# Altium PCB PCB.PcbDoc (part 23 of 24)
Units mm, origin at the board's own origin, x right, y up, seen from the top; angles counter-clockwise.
Board outline 100 x 160 mm, 10 copper layers (TOP_L1, L2, L3, L4, L5, L6, L7, L8, L9, BOTTOM_L10), stack 1.946 mm thick; 1358 components, 1149 nets, 6777 pads, 10914 vias.
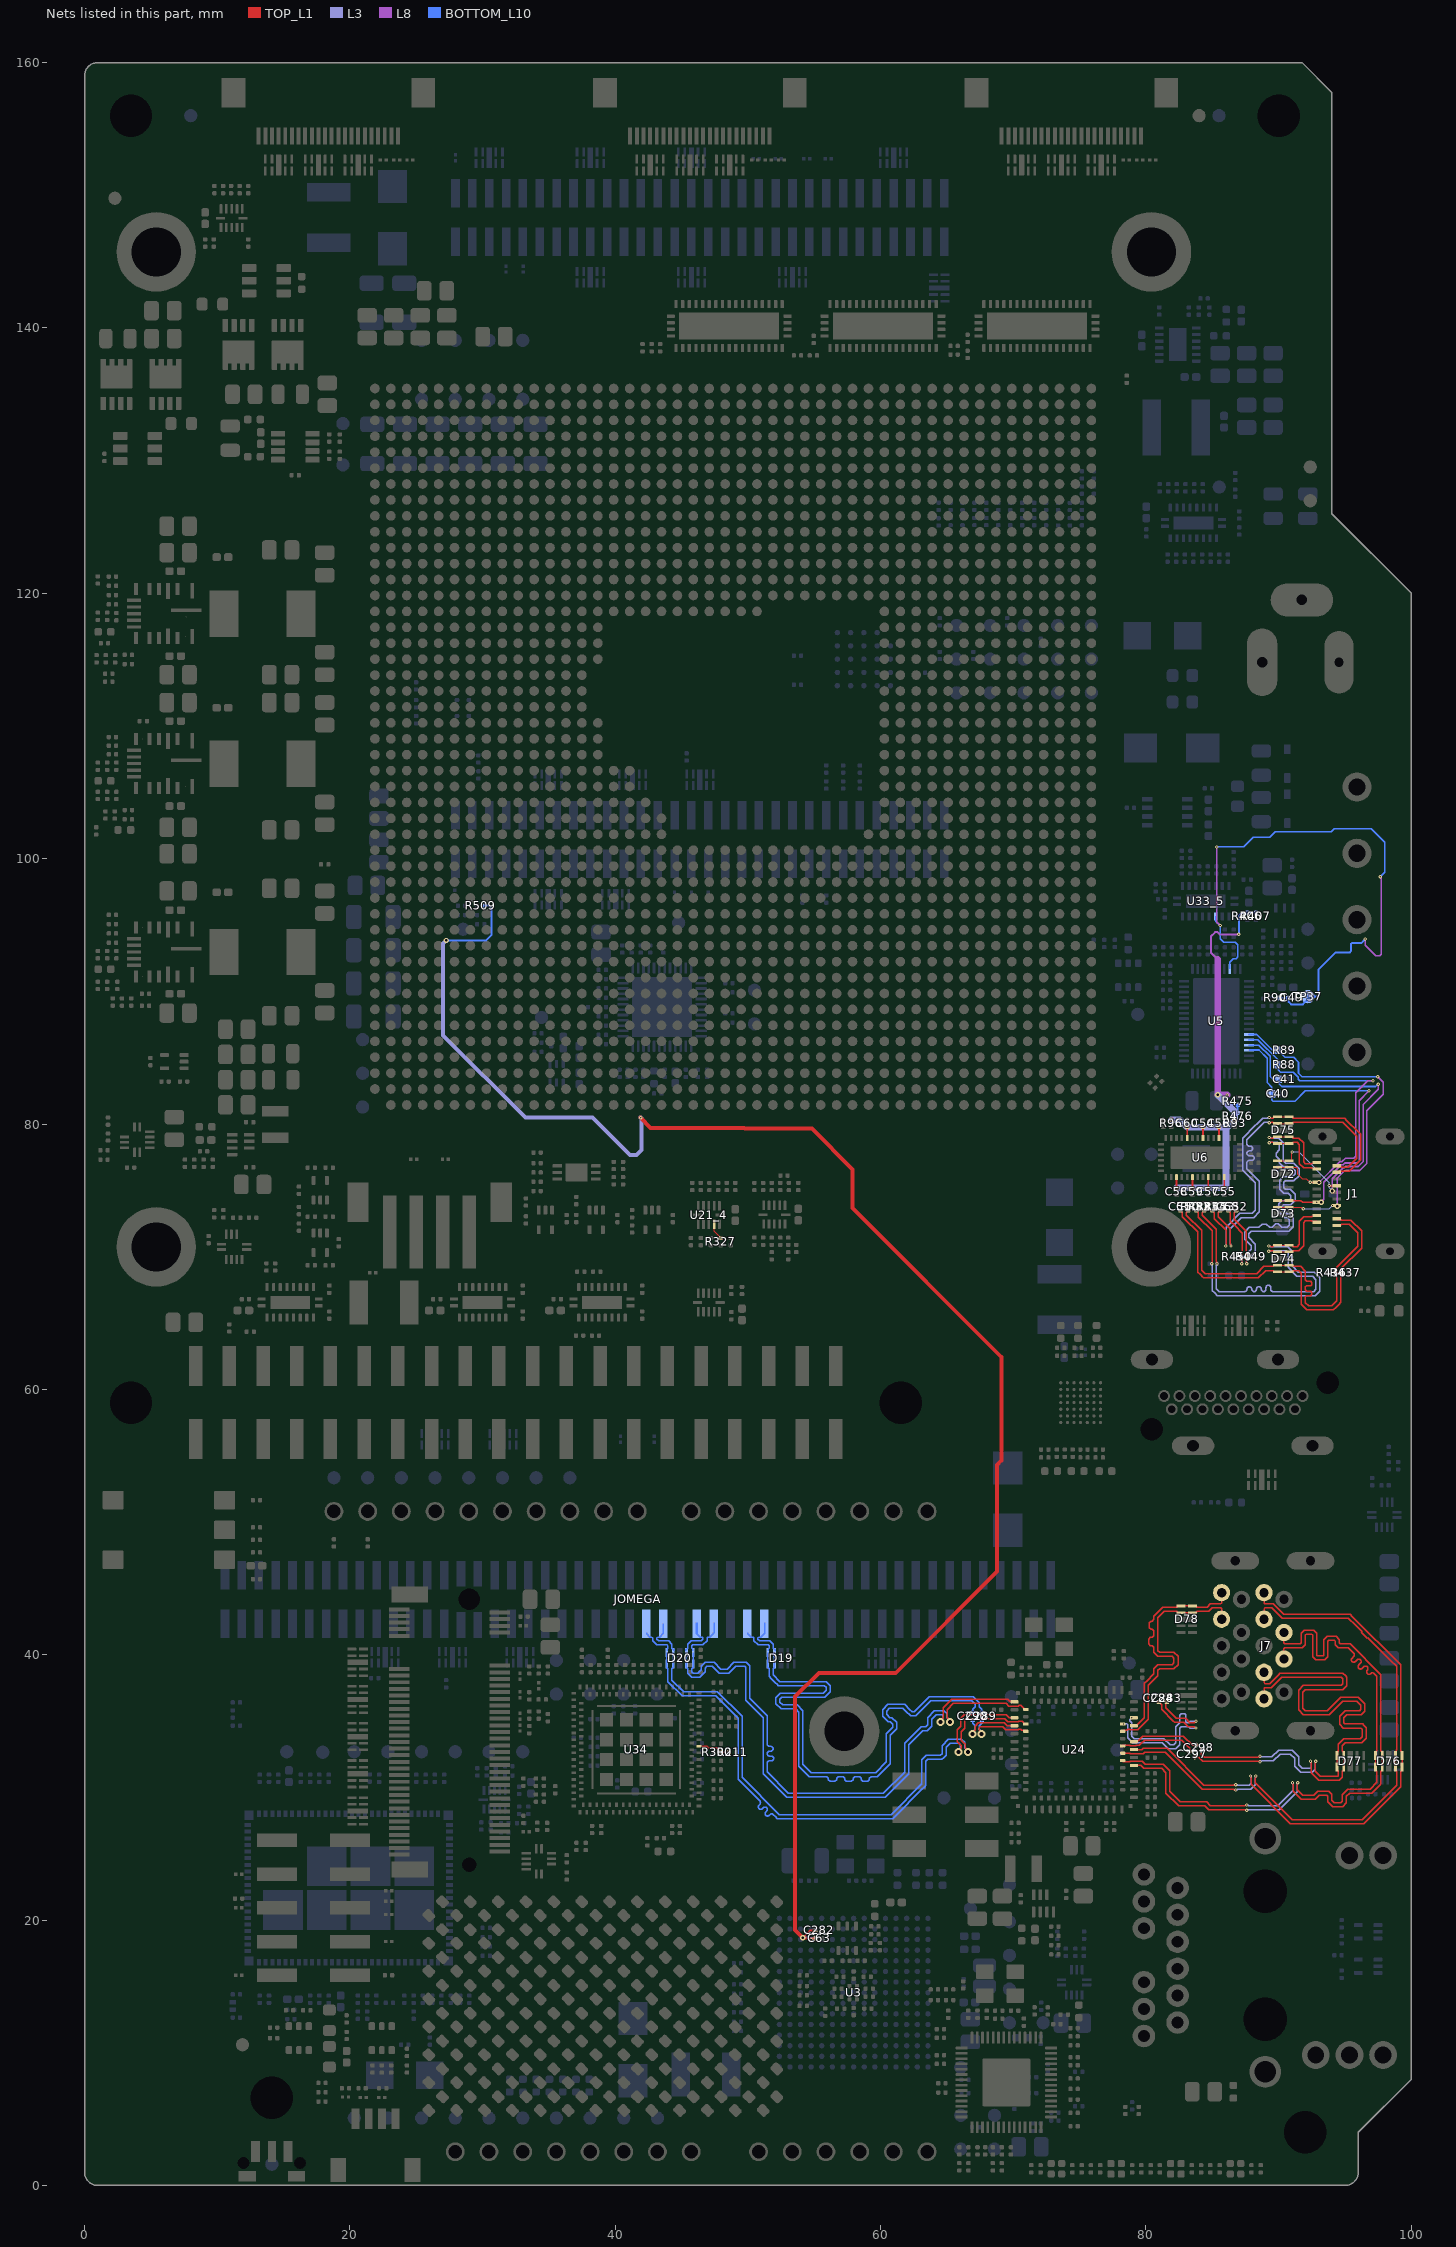
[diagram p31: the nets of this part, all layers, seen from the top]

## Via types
v1: diameter 0.25, hole 0.1, TOP_L1 to L2, tented both sides, 3439 vias
v2: diameter 0.25, hole 0.1, L2 to L3, tented both sides, 2256 vias
v3: diameter 0.25, hole 0.1, L9 to BOTTOM_L10, tented both sides, 1685 vias
v4: diameter 0.25, hole 0.1, L8 to L9, tented both sides, 1675 vias
v5: diameter 0.4, hole 0.2, L3 to L8, tented both sides, 1251 vias
v6: diameter 0.6, hole 0.3, TOP_L1 to BOTTOM_L10, tented both sides, 600 vias
v7: diameter 0.24, hole 0.1, TOP_L1 to L2, tented both sides, 8 vias

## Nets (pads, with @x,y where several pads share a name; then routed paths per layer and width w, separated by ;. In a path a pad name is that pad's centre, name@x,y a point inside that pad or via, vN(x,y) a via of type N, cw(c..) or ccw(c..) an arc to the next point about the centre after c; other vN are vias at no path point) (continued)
USB2_SSRX_N: D78.5 D78.6 J7.14 U24.A10 | length 18.6
  TOP_L1 w0.109: U24.A10@79.091,34.649 79.267,34.649 79.873,35.255 79.873,37.832 80.052,38.011 80.595,38.554 80.595,38.651 80.595,38.952 80.897,39.254 81.984,39.254 82.107,39.377 82.107,39.748 81.984,39.871 80.897,39.871 80.595,40.173 80.595,40.443 80.595,40.509 80.595,40.563 80.472,40.687 80.332,40.687 80.208,40.81 80.208,41.18 80.332,41.304 80.472,41.304 80.595,41.427 80.595,41.798 80.472,41.921 80.38,41.921 80.256,42.045 80.256,42.415 80.38,42.538 80.472,42.538 80.595,42.662 80.595,42.915 80.774,43.094 80.779,43.099 81.079,43.399 81.257,43.577 82.303,43.577 82.401,43.675 D78.6@82.638,43.675 D78.5@83.392,43.675 ; D78.5@83.513,43.675 83.751,43.675 83.849,43.577 84.602,43.577 84.852,43.827 85.636,43.827 85.7,43.891 J7.14@85.7,44.675
USB2_SSRX_P: D78.4 D78.7 J7.15 U24.B9 | length 18.7
  TOP_L1 w0.109: U24.B9@78.241,34.224 78.307,34.29 78.538,34.29 78.621,34.373 78.761,34.373 78.797,34.336 78.874,34.336 78.882,34.344 79.394,34.344 80.178,35.129 80.178,37.706 80.9,38.428 80.9,38.651 80.9,38.826 81.023,38.949 82.11,38.949 82.412,39.251 82.412,39.874 82.11,40.176 81.023,40.176 80.9,40.299 80.9,40.443 80.9,42.789 81.384,43.273 82.303,43.273 82.401,43.175 D78.7@82.638,43.175 D78.4@83.392,43.175 ; D78.4@83.513,43.175 83.751,43.175 83.849,43.273 84.729,43.273 84.979,43.523 85.636,43.523 85.7,43.459 J7.15@85.7,42.675
USB2_SSTX_26_N: C284.1 U24.B10 | length 12.1
  TOP_L1 w0.109: C284.1@80.975,36.425 81.172,36.229 81.172,35.889 82.072,34.99 82.161,34.9 82.862,34.9 83.188,34.575 83.637,34.575 83.737,34.475 v1(83.775,34.475)
  L3 w0.104: v2(78.301,34.774) 78.329,34.802 78.473,34.802 78.478,34.807 78.565,34.807 78.626,34.746 78.626,33.743 79.005,33.364 81.228,33.364 81.688,32.904 82.225,32.904 82.548,33.227 82.548,34.448 82.675,34.575 83.233,34.575 83.333,34.475 v1(83.775,34.475)
  other v1: 78.301,34.774
  other v2: 83.775,34.475
USB2_SSTX_26_P: C283.1 U24.A11 | length 12.5
  TOP_L1 w0.109: C283.1@81.575,36.425 81.477,36.327 81.477,36.016 82.034,35.459 82.288,35.205 82.988,35.205 83.314,34.88 83.642,34.88 83.737,34.975 v1(83.775,34.975)
  L3 w0.104: v2(78.921,35.249) 78.784,35.111 78.784,35.02 78.931,34.872 78.931,33.869 79.131,33.669 81.354,33.669 81.814,33.209 82.099,33.209 82.243,33.353 82.243,34.574 82.549,34.88 82.549,35.444 82.662,35.557 82.902,35.557 83,35.459 83,34.941 83.061,34.88 83.233,34.88 83.329,34.975 v1(83.775,34.975)
  other v1: 78.921,35.249
  other v2: 83.775,34.975
USB3_CAP_SSTX_N: C290.2 D19.5 D19.6 JOMEGA.38 | length 41.5
  BOTTOM_L10 w0.109: JOMEGA.38@49.998,41.643 49.998,41.569 50.237,41.33 50.385,41.33 50.449,41.266 50.449,41.049 50.76,40.738 51.53,40.738 51.594,40.674 51.594,40.498 51.538,40.442 D19.6@51.538,40.307 ; D19.6@51.496,40.137 D19.5@51.496,39.288 51.496,39.05 51.594,38.953 51.594,38.361 51.773,38.182 52.052,37.903 52.197,37.758 52.286,37.669 55.766,37.669 55.904,37.531 55.904,37.328 55.662,37.086 52.435,37.086 52.1,36.751 52.1,36.305 52.495,35.91 53.588,35.91 53.83,35.668 53.83,35.346 53.83,31.604 54.631,30.803 55.098,30.803 55.942,30.803 56.065,30.68 56.065,30.587 56.188,30.463 56.559,30.463 56.682,30.587 56.682,30.68 56.806,30.803 57.176,30.803 57.299,30.68 57.299,30.587 57.423,30.463 57.793,30.463 57.917,30.587 57.917,30.68 58.04,30.803 58.41,30.803 58.534,30.68 58.534,30.587 58.657,30.463 59.028,30.463 59.151,30.587 59.151,30.68 59.275,30.803 59.329,30.803 59.74,30.803 60.735,31.798 60.735,33.933 61.032,34.23 61.211,34.409 61.211,34.898 60.85,35.259 60.688,35.259 60.45,35.498 60.45,35.743 60.666,35.959 61.675,35.959 61.883,35.751 62.252,35.382 62.649,35.382 63.791,36.524 66.855,36.524 67.123,36.256 67.123,36.075 66.925,35.877 C290.2@66.925,35.622
USB3_CAP_SSTX_P: C289.2 D19.4 D19.7 JOMEGA.36 | length 41.1
  BOTTOM_L10 w0.109: JOMEGA.36@51.268,42.393 51.268,41.632 50.966,41.33 50.818,41.33 50.754,41.266 50.754,41.176 50.887,41.043 51.656,41.043 51.899,40.8 51.899,40.498 52.038,40.359 D19.7@52.038,40.307 ; D19.4@51.996,39.288 51.996,39.05 51.899,38.953 51.899,38.487 52.413,37.974 55.892,37.974 56.209,37.657 56.209,37.202 55.788,36.781 52.561,36.781 52.405,36.625 52.405,36.431 52.621,36.215 53.714,36.215 54.135,35.794 54.135,35.22 54.135,31.73 54.757,31.108 59.614,31.108 60.43,31.924 60.43,34.059 60.906,34.535 60.906,34.772 60.723,34.954 60.562,34.954 60.145,35.371 60.145,35.869 60.539,36.264 61.801,36.264 62.206,35.859 62.378,35.687 62.523,35.687 63.665,36.829 65.866,36.829 66.981,36.829 67.427,36.382 67.427,36.075 67.625,35.877 C289.2@67.625,35.622 ; D19.4@51.996,39.314 D19.7@51.996,40.163
USB3_D_N: D20.2 D20.9 JOMEGA.44 U24.A27 | length 46.5
  TOP_L1 w0.109: v6(64.514,34.929) 64.514,35.041 64.711,35.239 64.711,35.995 65.345,36.629 69.589,36.629 69.729,36.488 70.052,36.488 U24.A27@70.091,36.449
  BOTTOM_L10 w0.109: D20.9@45.325,40.306 45.325,40.358 45.464,40.498 45.464,40.8 45.707,41.043 46.476,41.043 46.609,41.175 46.609,41.266 46.545,41.33 46.397,41.33 46.168,41.559 46.095,41.632 JOMEGA.44@46.095,42.393 ; D20.2@45.366,39.313 D20.9@45.366,40.163 ; D20.9@45.366,40.137 D20.2@45.366,39.288 45.366,39.05 45.464,38.952 45.464,38.598 45.765,38.297 46.352,38.297 46.786,38.731 46.786,38.995 46.906,39.115 47.319,39.115 47.838,38.597 48.548,38.597 49.072,39.121 49.762,39.121 49.826,39.057 49.826,36.574 50.7,35.7 51.145,35.255 51.145,31.035 51.234,30.946 52.435,29.745 52.748,29.433 52.926,29.254 60.338,29.254 62.111,31.026 62.111,33.202 63.19,34.281 63.523,34.281 63.847,34.604 63.847,35.136 64.18,35.469 64.638,35.469 64.702,35.405 64.702,35.239 64.514,35.051 v6(64.514,34.929) ; JOMEGA.44@46.178,41.569 JOMEGA.44@46.178,42.393
USB3_D_P: D20.1 D20.10 JOMEGA.42 U24.B25 | length 46.5
  TOP_L1 w0.109: v6(65.214,34.929) 65.214,35.041 65.016,35.239 65.016,35.869 65.471,36.324 69.463,36.324 69.658,36.129 70.378,36.129 70.433,36.183 70.557,36.183 70.866,35.874 U24.B25@70.941,35.874
  BOTTOM_L10 w0.109: D20.10@45.825,40.307 45.825,40.442 45.769,40.498 45.769,40.674 45.833,40.738 46.602,40.738 46.914,41.049 46.914,41.266 46.978,41.33 47.126,41.33 47.365,41.569 JOMEGA.42@47.365,41.643 ; D20.10@45.866,40.137 D20.1@45.866,39.288 45.866,39.05 45.769,38.952 45.769,38.724 45.891,38.602 46.226,38.602 46.481,38.857 46.481,39.121 46.78,39.42 47.445,39.42 47.964,38.902 48.422,38.902 48.946,39.426 49.889,39.426 50.131,39.183 50.131,36.7 51.36,35.471 51.45,35.381 51.45,34.447 51.45,33.271 ccw(c51.631,33.271) 51.631,33.089 51.711,33.089 cw(c51.711,32.908) 51.711,32.726 51.631,32.726 ccw(c51.631,32.544) 51.631,32.363 51.751,32.363 cw(c51.751,32.181) 51.751,31.999 51.631,31.999 ccw(c51.631,31.818) 51.45,31.818 51.45,31.4 51.45,31.162 53.052,29.559 60.212,29.559 61.806,31.153 61.806,33.328 63.063,34.585 63.397,34.585 63.542,34.73 63.542,35.262 64.054,35.774 64.764,35.774 65.007,35.531 65.007,35.239 65.214,35.032 v6(65.214,34.929) ; JOMEGA.42@47.448,41.632 JOMEGA.42@47.448,42.393
USB3_SSRX_N: D20.5 D20.6 JOMEGA.50 U24.A29 | length 46.5
  TOP_L1 w0.109: v6(65.871,32.674) 65.871,32.786 66.069,32.983 66.069,33.143 65.957,33.256 65.778,33.434 65.778,34.328 65.785,34.334 66.048,34.598 66.048,35.228 66.291,35.47 69.485,35.47 69.698,35.257 70.083,35.257 U24.A29@70.091,35.249
  BOTTOM_L10 w0.109: JOMEGA.50@42.368,41.643 42.368,41.569 42.607,41.33 42.755,41.33 42.819,41.266 42.819,41.049 43.13,40.738 43.9,40.738 43.964,40.674 43.964,40.498 43.908,40.442 D20.6@43.908,40.307 ; D20.6@43.866,40.137 D20.5@43.866,39.288 43.866,39.05 43.964,38.952 43.964,37.965 45.03,36.898 47.574,36.898 49.255,35.218 49.255,30.619 49.277,30.597 49.316,30.558 50.893,28.981 cw(c50.765,28.852) 50.893,28.724 50.832,28.663 ccw(c50.961,28.534) 50.832,28.406 ccw(c50.961,28.534) 51.089,28.406 51.15,28.467 cw(c51.279,28.339) 51.407,28.467 cw(c51.279,28.339) 51.407,28.21 51.346,28.149 ccw(c51.475,28.021) 51.346,27.892 ccw(c51.475,28.021) 51.603,27.892 51.664,27.953 cw(c51.792,27.825) 51.921,27.953 51.959,27.915 52.046,27.828 52.225,27.649 60.911,27.649 61.089,27.828 63.077,29.815 63.327,30.065 63.416,30.154 63.416,31.953 63.569,32.106 64.617,32.106 64.756,32.245 64.935,32.423 64.935,33.029 65.23,33.324 65.954,33.324 66.018,33.26 66.018,32.954 65.871,32.807 v6(65.871,32.674)
USB3_SSRX_P: D20.4 D20.7 JOMEGA.48 U24.B27 | length 46.6
  TOP_L1 w0.109: v6(66.571,32.674) 66.571,32.786 66.374,32.983 66.374,33.27 66.083,33.56 66.083,34.202 66.09,34.208 66.353,34.471 66.353,35.102 66.417,35.166 69.358,35.166 69.595,34.929 70.378,34.929 70.422,34.973 70.668,34.973 70.866,34.774 U24.B27@70.941,34.774
  BOTTOM_L10 w0.109: JOMEGA.48@43.606,42.35 43.606,41.6 43.336,41.33 43.188,41.33 43.124,41.266 43.124,41.175 43.257,41.043 44.026,41.043 44.269,40.8 44.269,40.498 44.408,40.358 D20.7@44.408,40.306 ; D20.4@44.366,39.288 44.366,39.05 44.269,38.952 44.269,38.091 45.157,37.203 47.7,37.203 49.56,35.344 49.56,30.746 52.351,27.954 60.785,27.954 63.111,30.281 63.111,32.079 63.443,32.411 64.491,32.411 64.63,32.55 64.63,33.155 65.103,33.629 66.081,33.629 66.323,33.386 66.323,32.991 66.571,32.743 v6(66.571,32.674) ; D20.4@44.366,39.313 D20.7@44.366,40.163
USB3_SSTX_26_N: C290.1 U24.A30 | length 5
  TOP_L1 w0.109: v6(66.919,34.034) 66.919,34.146 67.116,34.344 67.116,34.617 67.359,34.86 69.316,34.86 69.542,34.633 70.076,34.633 U24.A30@70.091,34.649
  BOTTOM_L10 w0.109: v6(66.919,34.034) 66.919,34.167 67.116,34.365 67.116,34.645 66.925,34.836 C290.1@66.925,35.072
USB3_SSTX_26_P: C289.1 U24.B28 | length 5.5
  TOP_L1 w0.109: v6(67.619,34.034) 67.619,34.146 67.421,34.344 67.421,34.491 67.485,34.555 69.19,34.555 69.416,34.329 70.378,34.329 70.422,34.373 70.562,34.373 70.645,34.29 70.876,34.29 U24.B28@70.941,34.224
  BOTTOM_L10 w0.109: v6(67.619,34.034) 67.619,34.167 67.421,34.365 67.421,34.645 67.625,34.849 C289.1@67.625,35.072
USB4_CAP_SSTX_N: C298.2 D77.2 D77.9 J7.8 | length 42.1
  TOP_L1 w0.109: C298.2@84.18,32.784 84.179,32.505 84.395,32.29 88.445,32.29 88.471,32.315 88.57,32.315 v1(88.597,32.342) ; J7.8@88.9,38.675 88.9,37.891 88.964,37.827 89.33,37.827 89.921,38.418 90.01,38.507 90.099,38.597 94.847,38.597 95.043,38.4 95.134,38.31 95.134,37.667 95.02,37.554 94.842,37.375 91.99,37.375 91.8,37.185 91.8,35.959 91.984,35.775 93.669,35.775 94.684,36.791 96.016,36.791 96.505,36.301 96.505,35.749 96.231,35.475 95.126,35.475 94.9,35.249 94.9,34.875 94.995,34.78 96.326,34.78 96.416,34.691 96.605,34.501 96.605,33.707 96.426,33.529 96.261,33.364 95.03,33.364 94.802,33.136 94.802,32.748 94.9,32.65 D77.9@94.9,32.412 D77.2@94.9,31.537 94.9,31.3 94.802,31.202 94.802,30.765 94.56,30.523 93.021,30.523 92.448,31.096 92.448,31.841 92.427,31.861 92.427,31.948 v2(92.4,31.975)
  L3 w0.104: v1(88.597,32.342) 88.645,32.295 89.477,32.295 90,32.818 91.011,32.818 91.516,32.313 91.516,31.706 91.785,31.437 92.387,31.437 92.448,31.498 92.448,31.841 92.428,31.861 92.428,31.947 v2(92.4,31.975)
  other v1: 92.4,31.975
  other v2: 88.597,32.342
USB4_CAP_SSTX_P: C297.2 D77.1 D77.10 J7.9 | length 41.3
  TOP_L1 w0.109: C297.2@83.686,32.29 83.964,32.29 84.268,31.985 88.455,31.985 88.471,31.969 88.57,31.969 v1(88.597,31.942) ; J7.9@88.9,36.675 88.9,37.459 88.964,37.523 89.456,37.523 90.226,38.292 94.721,38.292 94.739,38.274 94.829,38.184 94.829,37.793 94.716,37.68 91.864,37.68 91.495,37.311 91.495,35.833 91.858,35.47 93.795,35.47 94.811,36.486 95.889,36.486 95.9,36.475 96.2,36.175 96.2,35.875 96.105,35.78 95,35.78 94.595,35.375 94.595,34.749 94.869,34.475 96.2,34.475 96.3,34.375 96.3,33.833 96.135,33.669 94.904,33.669 94.498,33.262 94.498,32.748 94.4,32.65 D77.10@94.4,32.412 D77.1@94.4,31.537 94.4,31.3 94.498,31.202 94.498,30.891 94.434,30.827 93.148,30.827 92.752,31.223 92.752,31.841 92.773,31.861 92.773,31.948 v2(92.8,31.975)
  L3 w0.104: v1(88.597,31.942) 88.625,31.97 88.711,31.97 88.731,31.99 89.603,31.99 90.126,32.513 90.884,32.513 91.211,32.187 91.211,31.58 91.659,31.132 92.513,31.132 92.752,31.371 92.752,31.841 92.772,31.861 92.772,31.947 v2(92.8,31.975)
  other v1: 92.8,31.975
  other v2: 88.597,31.942
USB4_D_N: D76.1 D76.10 J7.2 U24.A5 | length 47.3
  TOP_L1 w0.109: U24.A5@79.091,31.649 79.107,31.665 79.599,31.665 79.725,31.539 79.814,31.449 81.17,31.449 81.499,31.12 81.499,29.57 82.469,28.6 84.447,28.6 84.724,28.323 87.466,28.323 87.486,28.302 87.573,28.302 v1(87.6,28.275) ; J7.2@90.4,39.675 90.4,40.459 90.464,40.523 91.5,40.523 91.77,40.523 92.013,40.765 92.013,41.494 92.067,41.549 92.505,41.549 92.56,41.494 92.56,39.85 92.793,39.617 93.483,39.617 93.717,39.85 93.717,41.017 93.771,41.072 94.209,41.072 94.264,41.017 94.264,40.765 94.506,40.523 95.252,40.523 95.276,40.499 95.356,40.419 95.395,40.38 95.652,40.123 cw(c95.523,39.995) 95.652,39.866 95.53,39.744 ccw(c95.658,39.616) 95.53,39.487 ccw(c95.658,39.616) 95.787,39.487 95.909,39.609 cw(c96.037,39.481) 96.166,39.609 cw(c96.037,39.481) 96.166,39.353 96.045,39.232 ccw(c96.173,39.103) 96.045,38.975 ccw(c96.173,39.103) 96.302,38.975 96.422,39.096 cw(c96.551,38.967) 96.679,39.096 cw(c96.551,38.967) 96.679,38.839 ccw(c96.808,38.71) 96.679,38.582 ccw(c96.808,38.71) 96.936,38.582 cw(c97.064,38.454) 97.193,38.582 97.398,38.377 97.398,38.263 97.398,32.748 97.3,32.65 D76.10@97.3,32.412 D76.1@97.3,31.537 97.3,31.3 97.398,31.202 97.398,30.369 96.903,29.874 95.212,29.874 94.979,29.641 94.8,29.462 94.8,28.952 94.691,28.843 94.191,28.843 94.005,29.029 94.005,29.477 93.762,29.72 92.945,29.72 92.8,29.575 92.711,29.486 92.625,29.4 91.83,29.4 91.393,29.837 91.393,30.214 91.413,30.235 91.413,30.322 v2(91.44,30.349)
  L3 w0.104: v1(87.6,28.275) 87.628,28.303 87.714,28.303 87.734,28.323 90.045,28.323 91.393,29.67 91.393,30.215 91.412,30.235 91.412,30.321 v2(91.44,30.349)
  other v1: 91.44,30.349
  other v2: 87.6,28.275
USB4_D_P: D76.2 D76.9 J7.3 U24.B5 | length 47.3
  TOP_L1 w0.109: U24.B5@78.241,31.974 78.29,31.925 78.761,31.925 78.805,31.969 79.725,31.969 79.941,31.754 81.296,31.754 81.804,31.246 81.804,29.696 82.192,29.308 82.3,29.2 82.595,28.905 84.573,28.905 84.85,28.627 87.466,28.627 87.486,28.648 87.573,28.648 v1(87.6,28.675) ; J7.3@90.4,41.675 90.4,40.891 90.464,40.827 91.5,40.827 91.644,40.827 91.708,40.891 91.708,41.62 91.941,41.853 92.631,41.853 92.865,41.62 92.865,39.977 92.919,39.922 93.357,39.922 93.412,39.977 93.412,41.144 93.645,41.377 94.335,41.377 94.569,41.144 94.569,40.891 94.633,40.827 95.276,40.827 95.379,40.827 97.702,38.504 97.702,32.748 97.8,32.65 D76.9@97.8,32.412 D76.2@97.8,31.537 97.8,31.3 97.702,31.202 97.702,30.546 97.702,30.243 97.029,29.57 95.338,29.57 95.105,29.336 95.105,28.826 94.817,28.538 94.064,28.538 93.7,28.902 93.7,29.351 93.636,29.415 93.071,29.415 92.751,29.095 91.703,29.095 91.088,29.71 91.088,30.214 91.067,30.235 91.067,30.322 v1(91.04,30.349)
  L3 w0.104: v1(87.6,28.675) 87.628,28.647 87.714,28.647 87.734,28.627 89.919,28.627 91.088,29.796 91.088,30.215 91.068,30.235 91.068,30.321 v1(91.04,30.349)
  other v2: 87.6,28.675 91.04,30.349
USB4_SSRX_N: D76.5 D76.6 J7.5 U24.A7 | length 47.3
  TOP_L1 w0.109: U24.A7@79.091,32.849 79.107,32.833 79.672,32.833 79.786,32.947 81.584,32.947 84.371,30.16 86.631,30.16 86.652,30.181 86.739,30.181 v2(86.766,30.208) ; v1(87.882,30.86) 87.909,30.834 87.909,30.734 87.93,30.713 87.93,30.228 90.89,27.268 96.424,27.268 99.202,30.046 99.202,31.202 99.3,31.3 D76.5@99.3,31.537 99.3,32.65 99.186,32.764 99.186,39.255 95.562,42.88 95.383,43.058 91.848,43.058 90.379,43.058 89.61,43.827 88.964,43.827 88.9,43.891 J7.5@88.9,44.675
  L3 w0.104: v2(86.766,30.208) 86.794,30.18 86.88,30.18 86.9,30.16 87.782,30.16 87.93,30.308 87.93,30.727 87.91,30.746 87.91,30.833 v1(87.882,30.86)
  other v1: 86.766,30.208
  other v2: 87.882,30.86
USB4_SSRX_P: D76.4 D76.7 J7.6 U24.B6 | length 47.3
  TOP_L1 w0.109: U24.B6@78.241,32.574 78.759,32.574 78.805,32.529 79.798,32.529 79.912,32.642 81.458,32.642 84.245,29.856 86.631,29.856 86.652,29.835 86.739,29.835 v2(86.766,29.808) ; v1(88.282,30.86) 88.255,30.834 88.255,30.734 88.234,30.713 88.234,30.354 91.016,27.573 96.298,27.573 98.898,30.173 98.898,31.202 98.8,31.3 D76.4@98.8,31.537 D76.7@98.8,32.412 98.845,32.458 98.845,32.786 98.881,32.822 98.881,39.129 98.413,39.598 98.374,39.636 96.717,41.294 96.664,41.241 96.227,41.677 96.28,41.73 95.844,42.167 95.805,42.205 95.257,42.753 90.253,42.753 89.483,43.523 88.964,43.523 88.9,43.459 J7.6@88.9,42.675
  L3 w0.104: v2(86.766,29.808) 86.794,29.836 86.88,29.836 86.9,29.856 87.908,29.856 88.234,30.182 88.234,30.727 88.254,30.746 88.254,30.833 v1(88.282,30.86)
  other v1: 86.766,29.808
  other v2: 88.282,30.86
USB4_SSTX_26_N: C298.1 U24.A8 | length 5.2
  TOP_L1 w0.109: U24.A8@79.091,33.449 79.157,33.515 79.414,33.515 79.478,33.579 79.592,33.693 79.771,33.872 82.813,33.872 83.512,33.172 C298.1@83.791,33.172
USB4_SSTX_26_P: C297.1 U24.B7 | length 5.8
  TOP_L1 w0.109: U24.B7@78.241,33.124 78.29,33.173 78.761,33.173 78.805,33.129 79.221,33.129 79.25,33.158 79.489,33.158 79.604,33.274 79.897,33.567 82.687,33.567 83.297,32.957 C297.1@83.297,32.679
USBC_CC1: C40.2 D73.5 D73.6 J1.A5 U5.40 | length 26.4
  TOP_L1 w0.086: D73.6@89.907,74.229 D73.5@90.782,74.229
  TOP_L1 w0.109: D73.5@90.782,74.229 91.676,74.229 91.801,74.104 J1.A5@92.863,74.104
  L3 w0.109: v1(92.864,74.103) 92.866,74.102 93.21,74.102 v5(93.211,74.1)
  L8 w0.127: v5(93.211,74.1) 93.211,74.147 93.4,74.336 93.4,75.608 94.725,76.933 94.857,76.933 94.986,77.062 95.922,77.062 96.071,77.21 96.071,81.759 v4(96.811,82.5)
  BOTTOM_L10 w0.127: U5.40@87.791,85.577 88.516,85.577 89.132,84.962 89.132,83.132 89.483,82.78 C40.2@89.483,82.267 89.483,81.817 89.578,81.723 91.229,81.723 92.006,82.5 v4(96.811,82.5)
  other v2: 92.864,74.103
  other v3: 96.811,82.5
USBC_CC2: C41.2 D72.5 D72.6 J1.B5 U5.39 | length 28.7
  TOP_L1 w0.086: D72.6@89.907,77.229 D72.5@90.782,77.229 ; D72.5@90.982,77.229 90.979,77.232 90.979,77.838 v2(91.032,77.891) ; v1(93.819,75.359) 94.371,75.359 J1.B5@94.376,75.354
  L3 w0.086: v2(91.032,77.891) 91.514,77.891 93.819,75.586 v1(93.819,75.359) 93.819,75.185 94.041,74.963 v5(94.031,74.953)
  L8 w0.127: v5(94.031,74.953) 94.031,75.872 94.865,76.706 94.951,76.706 95.038,76.793 95.991,76.793 96.367,77.169 96.367,81.467 97.511,82.611 v4(97.511,83)
  BOTTOM_L10 w0.127: U5.39@87.753,85.947 88.509,85.947 89.359,85.097 89.359,83.576 89.568,83.367 C41.2@89.803,83.367 ; C41.2@90.029,83.341 90.029,83.024 90.231,82.822 97.3,82.822 97.478,83 v4(97.511,83)
  other v1: 91.032,77.891
  other v2: 93.819,75.359
  other v3: 97.511,83
USBC_SBU1: D72.4 D72.7 J1.A8 R88.2 U5.38 | length 25.6
  TOP_L1 w0.086: D72.7@89.907,76.729 D72.4@90.782,76.729 91.326,76.729 91.451,76.604 91.451,76.204 91.775,75.881 92.097,75.881 v2(92.373,75.604) J1.A8@92.876,75.604
  L3 w0.086: v2(92.373,75.604) 93.026,75.604 v5(93.036,75.594)
  L8 w0.127: v5(93.036,75.594) 94.602,77.16 94.763,77.16 95.031,77.428 95.652,77.428 95.801,77.576 95.801,82.351 96.705,83.256 v4(97.112,83.256)
  BOTTOM_L10 w0.127: U5.38@87.753,86.347 87.756,86.344 88.432,86.344 89.92,84.857 89.92,84.688 89.779,84.547 R88.2@89.779,84.483 ; R88.2@89.963,84.467 89.963,84.077 90.14,83.9 91.097,83.9 91.48,83.517 91.48,83.368 91.591,83.256 v4(97.112,83.256)
  other v1: 92.373,75.604
  other v3: 97.112,83.256
USBC_SBU2: D73.4 D73.7 J1.B8 R89.2 U5.37 | length 28.2
  TOP_L1 w0.086: D73.7@89.907,73.729 D73.4@90.782,73.729 91.718,73.729 91.836,73.611 v2(91.847,73.611)
  L3 w0.086: v2(91.847,73.611) 91.848,73.61 93.807,73.61 v1(94.051,73.854) 94.078,73.827 94.384,73.827 v5(94.411,73.8)
  L8 w0.127: v5(94.411,73.8) 94.411,75.927 94.963,76.479 95.045,76.479 95.065,76.498 96.11,76.498 96.629,77.018 96.629,80.999 97.871,82.241 97.871,83.154 v4(97.468,83.556)
  BOTTOM_L10 w0.127: U5.37@87.753,86.747 88.355,86.747 89.535,85.567 89.928,85.567 90.472,85.023 91.13,85.023 91.5,84.653 91.5,83.817 91.761,83.556 v4(97.468,83.556)
  other v1: 91.847,73.611
  other v2: 94.051,73.854
  other v3: 97.468,83.556
USBC_SSRX1_N: C51.2 D74.1 D74.10 J1.B10 R437.1 | length 27.6
  TOP_L1 w0.086: D74.10@89.907,68.859 D74.1@90.782,68.859
  TOP_L1 w0.109: C51.2@82.6,73.492 82.748,73.345 82.748,73.012 82.926,72.833 83.895,71.864 83.895,68.84 84.074,68.661 84.148,68.587 84.246,68.489 84.335,68.4 88.459,68.4 88.473,68.414 89.016,68.957 89.572,68.957 89.67,68.859 D74.10@89.907,68.859 ; D74.1@90.782,68.859 91.02,68.859 91.117,68.957 91.52,68.957 91.712,68.764 91.712,66.41 92.134,65.988 94.123,65.988 94.302,66.167 94.511,66.376 94.689,66.554 94.689,69.086 96.251,70.647 96.251,71.648 96.251,71.944 95.438,72.756 94.878,72.756 94.742,72.756 94.715,72.784 94.446,72.784 J1.B10@94.376,72.854
USBC_SSRX1_P: C50.2 D74.2 D74.9 J1.B11 R436.1 | length 27.6
  TOP_L1 w0.086: D74.9@89.907,69.359 D74.2@90.782,69.359
  TOP_L1 w0.109: C50.2@83.2,73.492 83.052,73.345 83.052,73.138 84.2,71.991 84.2,68.966 84.461,68.705 88.333,68.705 88.346,68.719 88.889,69.261 89.572,69.261 89.67,69.359 D74.9@89.907,69.359 ; D74.2@90.782,69.359 91.02,69.359 91.117,69.261 91.646,69.261 92.017,68.891 92.017,68.246 92.113,68.15 92.401,68.15 92.505,68.046 92.505,67.896 92.409,67.8 92.1,67.8 92.017,67.717 92.017,67.5 92.113,67.404 92.401,67.404 92.505,67.3 92.505,67.15 92.409,67.054 92.1,67.054 92.017,66.971 92.017,66.536 92.26,66.293 93.997,66.293 94.385,66.68 94.385,69.212 95.946,70.773 95.946,71.818 95.312,72.452 95.004,72.452 94.742,72.452 94.715,72.424 94.446,72.424 J1.B11@94.376,72.354
USBC_SSRX2_N: C53.2 D75.1 D75.10 J1.A10 R450.1 | length 27.2
  TOP_L1 w0.086: D75.10@89.907,78.536 D75.1@90.782,78.536
  TOP_L1 w0.109: C53.2@86.2,73.492 86.348,73.345 86.348,72.687 86.684,72.35 87.252,71.783 87.252,69.583 v1@87.232,69.564 ; v2(89.283,78.586) 89.31,78.613 89.397,78.613 89.418,78.634 ; 89.435,78.634 89.572,78.634 89.67,78.536 D75.10@89.907,78.536 ; D75.1@90.782,78.536 91.02,78.536 91.117,78.634 91.382,78.634 91.567,78.449 91.567,77.021 91.885,76.702 92.51,76.702 92.537,76.674 92.806,76.674 J1.A10@92.876,76.604
  L3 w0.104: v2(87.205,69.463) 87.233,69.491 87.233,69.577 87.253,69.597 87.253,69.865 87.935,70.547 87.935,70.826 87.431,71.33 87.431,71.847 87.792,72.207 88.504,72.207 88.744,72.446 89.071,72.446 89.31,72.207 89.507,72.207 89.763,72.463 89.985,72.463 90.242,72.207 90.634,72.207 90.805,72.379 90.805,72.798 90.685,72.918 90.47,72.918 90.291,73.097 90.176,73.212 89.997,73.39 89.997,73.983 90.237,74.222 90.772,74.222 90.928,74.378 90.928,74.586 90.732,74.781 90.376,74.781 90.071,75.087 90.071,75.746 90.354,76.029 91.022,76.029 91.231,76.239 91.231,76.489 91,76.721 90.422,76.721 90.057,77.085 90.057,77.336 89.814,77.579 89.814,77.814 90.057,78.057 90.057,78.464 89.887,78.634 89.417,78.634 89.397,78.614 89.311,78.614 v2(89.283,78.586)
  other v1: 87.205,69.463 89.283,78.586
USBC_SSRX2_P: C52.2 D75.2 D75.9 J1.A11 R449.1 | length 27.2
  TOP_L1 w0.086: D75.9@89.907,79.036 D75.2@90.782,79.036
  TOP_L1 w0.109: C52.2@86.8,73.492 86.652,73.345 86.652,72.813 87.557,71.909 87.557,69.583 87.578,69.562 87.578,69.49 v2(87.605,69.463) ; v2(89.283,78.986) 89.31,78.959 89.397,78.959 89.418,78.938 ; 89.435,78.938 89.572,78.938 89.67,79.036 D75.9@89.907,79.036 ; D75.2@90.782,79.036 91.02,79.036 91.117,78.938 91.508,78.938 91.871,78.575 91.871,78.478 91.871,77.147 92.012,77.006 92.51,77.006 92.537,77.034 92.806,77.034 J1.A11@92.876,77.104
  L3 w0.104: v2(87.605,69.463) 87.577,69.491 87.577,69.577 87.558,69.597 87.558,69.738 88.24,70.42 88.24,70.953 87.736,71.456 87.736,71.72 87.918,71.902 90.76,71.902 91.11,72.252 91.11,72.924 90.812,73.223 90.596,73.223 90.302,73.517 90.302,73.856 90.363,73.917 90.898,73.917 91.233,74.252 91.233,74.712 90.859,75.086 90.502,75.086 90.376,75.213 90.376,75.62 90.48,75.724 91.148,75.724 91.536,76.112 91.536,76.615 91.126,77.025 90.548,77.025 90.362,77.212 90.362,78.59 90.014,78.938 89.417,78.938 89.397,78.958 89.311,78.958 v2(89.283,78.986)
  other v1: 87.605,69.463 89.283,78.986
USBC_SSTX1_N: D74.5 D74.6 J1.A3 R452.1 | length 27.2
  TOP_L1 w0.086: D74.6@89.907,70.859 D74.5@90.782,70.859
  TOP_L1 w0.109: R452.1@83.8,73.492 83.948,73.345 83.948,72.987 84.989,71.945 84.989,69.5 v2(84.952,69.463) ; v2(89.255,70.799) 89.282,70.772 89.395,70.772 89.406,70.761 89.572,70.761 89.67,70.859 D74.6@89.907,70.859 ; D74.5@90.782,70.859 91.02,70.859 91.117,70.761 91.382,70.761 91.567,70.946 91.567,72.688 91.885,73.006 92.51,73.006 92.537,73.034 92.806,73.034 J1.A3@92.876,73.104
  L3 w0.104: v2(84.952,69.463) 84.98,69.435 84.98,69.349 85,69.329 85,67.443 85.178,67.264 85.379,67.063 92.767,67.063 92.856,67.153 92.972,67.269 93.115,67.411 93.115,68.405 92.855,68.664 92.677,68.843 91.491,68.843 91.023,69.311 91.023,70.424 90.696,70.751 89.389,70.751 89.37,70.771 89.283,70.771 v2(89.255,70.799)
  other v1: 84.952,69.463 89.255,70.799
USBC_SSTX1_P: D74.4 D74.7 J1.A2 R451.1 | length 27.2
  TOP_L1 w0.086: D74.7@89.907,70.359 D74.4@90.782,70.359
  TOP_L1 w0.109: R451.1@84.4,73.492 84.252,73.345 84.252,73.113 84.8,72.566 84.908,72.458 85.294,72.071 85.294,69.608 85.325,69.577 85.325,69.528 85.345,69.508 v1@85.394,69.508 ; v2(89.255,70.399) 89.282,70.426 89.375,70.426 89.406,70.457 89.572,70.457 89.67,70.359 D74.7@89.907,70.359 ; D74.4@90.782,70.359 91.02,70.359 91.117,70.457 91.508,70.457 91.871,70.82 91.871,72.561 92.012,72.702 92.51,72.702 92.537,72.674 92.806,72.674 J1.A2@92.876,72.604
  L3 w0.104: v2(85.352,69.463) 85.324,69.435 85.324,69.349 85.304,69.329 85.304,67.569 85.505,67.368 86.389,67.368 87.432,67.368 ccw(c87.432,67.547) 87.611,67.547 cw(c87.79,67.547) 87.969,67.547 ccw(c88.148,67.547) 88.327,67.547 88.327,67.556 cw(c88.506,67.556) 88.686,67.556 88.686,67.547 ccw(c88.865,67.547) 89.044,67.547 89.044,67.673 cw(c89.223,67.673) 89.402,67.673 89.402,67.547 ccw(c89.581,67.547) 89.581,67.368 89.991,67.368 92.641,67.368 92.81,67.537 92.81,68.279 92.55,68.538 91.365,68.538 90.718,69.185 90.718,70.298 90.57,70.446 89.389,70.446 89.37,70.427 89.283,70.427 v2(89.255,70.399)
  other v1: 85.352,69.463 89.255,70.399
USBC_SSTX2_N: D75.5 D75.6 J1.B3 R454.1 | length 27.3
  TOP_L1 w0.086: D75.6@89.907,80.536 D75.5@90.782,80.536
  TOP_L1 w0.109: R454.1@85,73.492 85.159,73.333 85.159,72.875 86.052,71.983 86.052,70.919 86.031,70.899 86.031,70.826 v1(86.004,70.799) ; v2(89.283,80.486) 89.31,80.459 89.397,80.459 89.418,80.438 ; 89.435,80.438 89.572,80.438 89.67,80.536 D75.6@89.907,80.536 ; D75.5@90.782,80.536 91.02,80.536 91.117,80.438 91.404,80.438 91.405,80.44 92.004,80.44 92.005,80.441 94.967,80.441 95.145,80.262 96.008,79.399 96.187,79.221 96.187,77.31 95.329,76.452 94.878,76.452 94.742,76.452 94.715,76.424 94.446,76.424 J1.B3@94.376,76.354
  L3 w0.104: v2@86.032,70.913 86.042,70.923 86.042,72.228 86.221,72.407 86.891,73.077 87.069,73.256 87.994,73.256 88.249,73.51 88.249,75.567 87.3,76.516 87.3,78.942 88.249,79.891 88.339,79.98 88.458,80.1 88.618,80.26 88.797,80.438 89.149,80.438 89.169,80.458 89.255,80.458 v2(89.283,80.486)
  other v1: 89.283,80.486
  other v2: 86.004,70.799
USBC_SSTX2_P: D75.4 D75.7 J1.B2 R453.1 | length 27.2
  TOP_L1 w0.086: D75.7@89.907,80.036 D75.4@90.782,80.036
  TOP_L1 w0.109: R453.1@85.599,73.492 85.464,73.357 85.464,73.001 85.9,72.566 86.008,72.458 86.357,72.109 86.357,70.919 86.377,70.899 86.377,70.826 v2(86.404,70.799) ; v2(89.283,80.086) 89.31,80.113 89.397,80.113 89.418,80.134 ; 89.435,80.134 89.572,80.134 89.67,80.036 D75.7@89.907,80.036 ; D75.4@90.782,80.036 91.02,80.036 91.117,80.134 91.53,80.134 91.532,80.135 92.004,80.135 92.005,80.134 92.007,80.136 94.841,80.136 95.882,79.095 95.882,77.436 95.202,76.756 95.004,76.756 94.742,76.756 94.715,76.784 94.446,76.784 J1.B2@94.376,76.854
  L3 w0.104: v2(86.404,70.799) 86.376,70.827 86.376,70.93 86.347,70.959 86.347,72.102 87.196,72.951 88.121,72.951 88.554,73.384 88.554,75.693 87.605,76.643 87.605,76.666 87.605,77.077 cw(c87.784,77.077) 87.784,77.256 87.969,77.256 ccw(c87.969,77.435) 87.969,77.614 87.784,77.614 cw(c87.784,77.793) 87.784,77.972 87.849,77.972 ccw(c87.849,78.151) 87.849,78.33 87.784,78.33 cw(c87.784,78.509) 87.605,78.509 87.605,78.816 87.707,78.918 88.923,80.134 89.149,80.134 89.169,80.114 89.255,80.114 v2(89.283,80.086)
  other v1: 86.404,70.799 89.283,80.086
VBAT: C63.2 C282.2 R509.2 U3.D3 | length 127.8
  TOP_L1 w0.15: C63.2@55.088,18.629 55.021,18.629 55.009,18.617 54.208,18.617 54.151,18.675 v5(54.123,18.675) 54.678,19.229 C282.2@55.088,19.229
  TOP_L1 w0.3: v1(41.91,80.473) 42.671,79.712 49.71,79.712 49.772,79.65 54.813,79.65 57.879,76.584 57.879,73.653 69.091,62.441 69.091,54.631 68.764,54.304 68.764,46.261 61.138,38.636 55.345,38.636 53.56,36.85 53.56,19.238 v5(54.123,18.675)
  L3 w0.3: v5(27.266,93.838) 27.024,93.595 27.024,86.668 33.219,80.473 38.295,80.473 41.093,77.675 41.598,77.675 41.965,78.042 41.965,80.418 v1(41.91,80.473)
  L8 w0.15: v5(54.123,18.675) 54.591,18.675 54.736,18.529 v3(54.763,18.529)
  BOTTOM_L10 w0.15: v5(27.266,93.838) 30.269,93.838 30.683,94.251 30.683,96.251 30.483,96.451 R509.2@30.133,96.451
  other v1: 54.123,18.675
  other v2: 54.123,18.675 41.91,80.473
  other v3: 27.266,93.838
  other v4: 54.763,18.529 27.266,93.838
VC1_EN_25: R211.1 R300.2 U34.W1 | length 2.4
  TOP_L1 w0.1: U34.W1@46.311,33.099 46.889,33.099 47.019,32.969 47.641,32.969 R300.2@47.961,32.649 R211.1@48.561,32.649
VCC_32: C54.2 C55.2 C56.2 C57.2 C58.2 C59.2 C60.2 R93.1 R96.1 R406.1 R407.1 R475.1 R476.1 U6.4 U6.7 U6.10 U6.23 U6.26 U6.29 U6.32 | length 41.6
  TOP_L1 w0.127: v2(82.3,75.187) U6.23@82.3,75.99 ; U6.10@83.1,78.94 v1(83.1,79.766) ; v1(83.5,75.187) U6.26@83.5,75.99 ; U6.7@84.3,78.94 v1(84.3,79.766) ; v1(84.7,75.187) U6.29@84.7,75.99 ; U6.4@85.5,78.94 v2(85.5,79.766) ; v1(85.9,75.187) U6.32@85.9,75.99
  L3 w0.5: v2(81.9,80.316) 82.55,80.316 v1(83.1,79.766) v1(84.3,79.766) v2(85.5,79.766) 86.15,79.766 v1(86.7,80.316) 86.7,80.9 v5(85.4,82.2) ; v2(82.3,75.187) v1(84.7,75.187) v1(85.9,75.187) 86.029,75.316 86.029,79.766
  L8 w0.15: 85.4,92.4 84.9,92.9 84.9,94.163 85.204,94.466 85.39,94.466 85.557,94.3 v4(87,94.3)
  L8 w0.5: 85.4,92.4 v5(85.4,82.2) 85.41,82.19 v4(86.132,82.19)
  BOTTOM_L10 w0.15: v4(86.132,82.19) 86.132,81.618 86.303,81.447 R475.1@86.903,81.447 R476.1@86.903,80.847 ; v4(87,94.3) 87,95.7 87.222,95.922 R406.1@87.634,95.922 R407.1@88.284,95.922
  other v1: 82.3,75.187 85.5,79.766 81.9,80.316
  other v2: 83.5,75.187 84.7,75.187 85.9,75.187 83.1,79.766 84.3,79.766 86.7,80.316
  other v3: 86.132,82.19 87,94.3
WAKE_N_3V3_24: R327.2 U21_4.10 | length 1.2
  TOP_L1 w0.084: U21_4.10@47.45,72.441 47.463,72.428 47.463,71.899 R327.2@47.95,71.412
XRES_33: C49.2 R90.2 TP37.X U5.24 U33_5.14 | length 46.3
  L8 w0.1: v4(85.342,100.88) 85.342,95.221 v4(85.598,94.966) ; v3(96.524,93.945) 96.524,93.487 97.311,92.7 97.611,92.7 97.716,92.805 97.716,98.487 97.695,98.508 97.695,98.614 v4(97.667,98.642)
  BOTTOM_L10 w0.1: U33_5.14@85.253,95.645 85.253,95.289 85.576,94.966 v4(85.598,94.966) 85.587,94.955 85.587,93.973 85.864,93.696 86.722,93.696 86.923,93.495 86.923,92.602 86.788,92.467 86.581,92.467 86.303,92.189 U5.24@86.303,91.697 ; v4(85.342,100.88) 85.358,100.895 87.369,100.895 88.085,101.612 89.32,101.612 89.748,102.04 93.981,102.04 94.196,102.254 96.97,102.254 98.005,101.219 98.005,98.981 v4(97.667,98.642)
  BOTTOM_L10 w0.15: R90.2@90.003,89.497 C49.2@90.703,89.497 ; C49.2@90.703,89.447 90.75,89.4 90.75,89.201 90.934,89.017 91.817,89.017 TP37.X@92.4,89.6 ; TP37.X@92.2,89.6 TP37.X@92.4,89.6 ; v3(96.524,93.945) 96.218,93.639 95.519,93.639 95.445,93.565 95.445,93.028 95.336,92.92 94.27,92.92 93.005,91.654 93.005,89.688 92.917,89.6 TP37.X@92.4,89.6
  other v3: 85.598,94.966 97.667,98.642 85.342,100.88
  other v4: 96.524,93.945
pads on no net: Fiducial_1.1 Fiducial_2.1 Fiducial_3.1 Fiducial_4.1 Fiducial_5.1 Fiducial_6.1 J1.FIXING J2.NC J2.SH1 J4.14 J4.NC J10.6 J10.8 J10.10 J10.20 J10.24 J10.26 J10.28 J10.30 J10.34 J10.36 J10.44 J10.46 J10.48 J10.56 J10.58 J10.67 J10.68 J10.69 J10.73 J10.MH1 J10.MH2 JMISC.60 MODULE1.A46 MODULE1.BB45 MODULE1.BF1 MODULE1.BF46 PB2.NC1 PB2.NC2 R125.1 R441.1 R442.1 R443.1 R444.1 R445.1 R446.1 R447.1 R448.1 R462.1 R469.2 R470.2 U1.52 U2.A2 U2.A3 U2.B1 U2.B5 U2.C5 U3.A2 U3.A3 U3.A10 U3.A11 U3.A12 U3.A13 U3.B10 U3.B11 U3.B13 U3.C1 U3.C3 U3.C5 U3.C9 U3.C10 U3.C11 U3.C14 U3.D6 U3.D9 U3.D10 U3.D11 U3.D13 U3.D14 U3.D15 U3.E9 U3.E12 U3.F1 U3.F2 U3.F4 U3.F5 U3.G2 U3.G3 U3.G5 U3.H1 U3.H4 U3.H5 U3.H11 U3.J4 U3.K1 U3.L7 U3.L12 U3.M4 U3.M5 U3.M6 U3.M9 U3.N4 U3.N5 U3.N6 U3.N7 U3.N8 U3.N9 U3.P5 U3.P6 U3.P7 U3.P8 U3.P9 U3.R4 U3.R5 U3.R6 U3.R7 U3.R8 U3.R10 U5.1 U5.2 U5.3 U5.4 U5.5 U5.6 U5.7 U5.8 U5.9 U5.10 U5.44 U8.1 U9.1 U10_1.9 U10_1.30 U10_2.9 U10_2.30 U10_3.9 U10_3.30 U11.6 U11.13 U12.1 U12.2 U12.9 U12.10 U12.13 U12.14 U12.15 U12.16 U12.21 U12.22 U12.24 U12.25 U12.46 U12.47 U12.48 U12.49 U12.50 U12.51 U12.52 U12.64 U12.65 U12.67 U13.6 U13.13 U14.6 U14.13 U14.16 U19.1 U23.16 U23.22 U23.23 U23.24 U23.26 U23.33 U23.34 U23.35 U24.A14 U24.A26 U24.A43 U24.A49 U24.B8 U24.B13 U24.B29 U24.B46 U24.B47 U24.B48 U25.1 U26.5 U27_1.12 U27_2.12 U27_3.12 U27_4.12 U27_5.12 U27_6.12 U30.5 U31.1 U32.1 U34.A1 U34.A3 U34.A15 U34.A33 U34.A35 U34.AB2 U34.AD34 U34.AE35 U34.AJ1 U34.AK2 U34.AL1 U34.AM2 U34.AN1 U34.AP1 U34.AP2 U34.AP4 U34.AP16 U34.AP24 U34.AP26 U34.AP32 U34.AP34 U34.AP35 U34.AR1 U34.AR3 U34.AR17 U34.AR21 U34.AR23 U34.AR25 U34.AR27 U34.AR29 U34.AR33 U34.AR35 U34.B1 U34.B2 U34.B8 U34.B12 U34.B20 U34.B24 U34.B28 U34.B34 U34.B35 U34.C1 U34.C35 U34.D2 U34.D34 U34.E1 U34.E35 U34.H2 U34.J1 U34.M34 U35.1 U36.1

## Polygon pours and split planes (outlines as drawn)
GND on L8 "NONET_L-01_P-001" (solid, remove dead copper, pour order 97): 0.161,1 0.161,159 cw(c1.161,159) 1.161,160 91.91,160 94.161,157.749 94.161,126 100.161,120 100.161,8 96.161,4 96.161,1 cw(c95.161,1) 95.161,0 1.161,0 cw(c1.161,1)
SOM_VREG_MDPX3_1P8 on L8 "NONET_L04_P-001" (solid, remove dead copper, pour order 72): 20.01,64.401 50.31,64.401 53.91,68.001 53.91,88.101 86.415,120.606 86.415,132.888 52.934,132.888 46.547,126.501 21.633,126.501 20.056,124.923
SOM_VREG_MDPX3_1P8 on L8 "NONET_L04_P-001" (solid, remove dead copper, pour order 67): 18.362,66.8 21.855,66.8 21.855,86.3 11.655,86.3 11.655,72.587 11.055,71.987 11.055,66.814
CYPD_VDDIO on L8 "CYPD_VDDIO_L08_P026" (solid, remove dead copper, pour order 26): 82.761,92.906 82.761,86.731 81.403,85.373 80.193,86.583 80.193,86.867 81.723,88.398 81.723,92.909
SOM_VREG_S5S_SPX3_1P8 on L8 "NONET_L04_P-001" (solid, remove dead copper, pour order 69): 53.731,115.471 53.731,112.036 59.633,112.036 61.198,113.601 62.9,113.601 64.71,115.411 64.71,122.718 64.71,126.58 61.507,126.58 59.461,124.534 59.461,121.201
GND on BOTTOM_L10 "C" (solid, remove dead copper, pour order 105): 0,1 0,159 cw(c1,159) 1,160 91.749,160 94,157.749 94,126 100,120 100,8 96,4 96,1 cw(c95,1) 95,0 1,0 cw(c1,1)
7V-24V on BOTTOM_L10 "NONET_L-01_P-001" (solid, remove dead copper, pour order 104): 98.402,111.836 92.813,111.836 92.124,112.525 92.124,117.125 91.213,118.036 82.948,118.036 82.948,112.69 82.948,106.224 88.432,106.224 88.755,105.902 88.755,102.036 98.402,102.036
+5V on BOTTOM_L10 "+5V_L10_P056" (solid, remove dead copper, pour order 56): 99.725,26.1 93.425,26.1 92.525,27 92.525,31.3 93.225,32 99.725,32
SOM_VREG_MDPX3_1P8 on BOTTOM_L10 "NONET_L04_P-001" (solid, remove dead copper, pour order 90): 76.761,131.901 76.761,123.801 71.01,123.801 71.01,120.801 87.81,120.801 87.81,131.901
+5V on BOTTOM_L10 "+5V_L10_P096" (solid, remove dead copper, pour order 96): 14.842,47.396 14.842,49.47 25.088,59.716 25.088,66.916 22.488,69.516 13.388,69.516 9.75,65.878 9.75,47.396
SOM_VREG_MDPX3_1P8 on BOTTOM_L10 "NONET_L04_P-001" (solid, remove dead copper, pour order 91): 76.61,104.001 79.524,101.087 83.224,101.087 83.71,100.601 83.71,97.801 77.813,97.801 75.956,99.658 75.956,100.481 75.127,101.31 75.21,101.393 75.21,104.001
+1V8 on BOTTOM_L10 "NONET_L04_P-001" (solid, remove dead copper, pour order 92): 73.926,15.3 75.581,15.3 75.581,50.296 86.004,50.296 86.004,47.947 84.526,46.3 84.526,35.412 86.158,33.608 86.158,25.877 84.881,24.6 79.482,24.6 78.626,23.744 78.626,14.7 73.926,14.7
NetC71_2 on BOTTOM_L10 "NETC71_2_L10_P095" (solid, remove dead copper, pour order 95): 82.515,61.139 79.215,61.139 78.53,61.824 78.53,66.641 71.833,66.641 71.833,62.489 75.915,62.489 76.353,62.052 76.353,57.839 79.965,57.839 82.515,57.839
PA_VBUS on BOTTOM_L10 "PA_VBUS_L10_P049" (solid, remove dead copper, pour order 49): 97.482,80.218 95.553,82.147 91.553,82.147 91.253,81.847 89.853,81.847 88.753,82.947 88.753,84.847 88.253,85.347 87.353,85.347 87.353,77.647 88.349,76.651 92.649,76.651 93.353,75.947 93.353,73.547 93.763,73.137 97.482,73.137
+3V3 on BOTTOM_L10 "+3V3_L10_P040" (solid, remove dead copper, pour order 40): 76.496,127.575 84.775,127.575 84.775,128.425 86.275,128.425 86.275,128.025 86.931,128.025 86.931,129.225 77.425,129.225 76.496,128.296
NetC354_1 on BOTTOM_L10 "NETC354_1_L10_P041" (solid, remove dead copper, pour order 41): 90.009,132.6 90.009,130.1 85.509,130.1 85.509,132.6
NetC350_2 on BOTTOM_L10 "NETC350_2_L10_P042" (solid, remove dead copper, pour order 42): 81.558,138.704 81.558,136.042 81.558,134.9 79.1,134.9 79.1,138.704
NetD43_2 on BOTTOM_L10 "NETD43_2_L10_P046" (solid, remove dead copper, pour order 46): 16.8,150.5 19.558,150.5 21.6,148.458 29.9,148.458 29.9,144.411 26.182,144.411 25.235,145.358 21.51,145.358 19.61,147.258 16.8,147.258
+3V3 on BOTTOM_L10 "+3V3_L10_P050" (solid, remove dead copper, pour order 50): 21.1,47.331 21.1,47.382 21.934,48.216 21.934,49.655 12.332,49.655 12.332,47.331
+5V on BOTTOM_L10 "+5V_L10_P070" (solid, remove dead copper, pour order 70): 14.8,96.6 14.8,89.2 17.8,89.2 18.97,88.03 18.97,85.6 21.06,85.6 21.06,96.6
CYPD_VDDIO on BOTTOM_L10 "CYPD_VDDIO_L10_P083" (solid, remove dead copper, pour order 83): 81.9,88.3 81.9,83.1 81.9,82.547 78.4,82.547 78.4,88.3
+3V3 on BOTTOM_L10 "+3V3_L10_P084" (solid, remove dead copper, pour order 84): 15.433,27.608 15.433,29.15 15.832,29.549 15.832,30.878 13.025,30.878 13.025,28.564 14.453,28.564 14.453,27.604
+3V3 on BOTTOM_L10 "+3V3_L10_P087" (solid, remove dead copper, pour order 87): 15.562,17.198 15.562,11.662 14.8,10.9 12.7,10.9 12.7,12.6 13.6,12.6 14.264,13.264 14.264,17.2
+3V3 on BOTTOM_L10 "NONET_L04_P-001" (solid, remove dead copper, pour order 93): 29.726,151.2 29.726,148.9 27.426,148.9 27.426,149.9 25.426,151.9 25.426,153.8 26.326,154.7 28.026,154.7 28.726,154 28.726,151.6 29.326,151.6
NetC147_2 on BOTTOM_L10 "NETC147_2_L10_P098" (solid, remove dead copper, pour order 98): 95,45.949 95,49.78 99.5,49.78 99.5,40.8 96.146,40.8 92.667,37.321 91.35,37.321 91.35,40.8 91.35,45.949
NetC35_2 on BOTTOM_L10 "NETC35_2_L10_P100" (solid, remove dead copper, pour order 100): 100,32.275 94.154,32.275 94.154,35.062 86.25,35.062 86.25,38.3 87.75,38.3 87.75,36.8 92.525,36.8 96.325,40.6 100,40.6
+1.28V on BOTTOM_L10 "NONET_L04_P-001" (solid, remove dead copper, pour order 101): 41.54,86.33 41.54,83.83 39.84,83.83 39.84,84.63 36.54,84.63 36.54,84.03 35.84,84.03 35.84,87.23 33.44,87.23 33.44,89.43 40.24,89.43 40.24,86.33
7V-24V on BOTTOM_L10 "NONET_L-01_P-001" (solid, remove dead copper, pour order 102): 64.902,44.936 64.902,49.136 65.966,50.2 74.223,50.2 74.223,46.038 73.121,44.936
7V-24V on BOTTOM_L10 "C" (solid, remove dead copper, pour order 53): 47.29,10.153 47.29,6.102 48.739,4.653 50.202,4.653 50.202,10.153
+5V on BOTTOM_L10 "+5V_L10_P066" (solid, remove dead copper, pour order 66): 97.39,50.1 94.537,50.1 94.537,48.1 90.39,48.1 90.39,51.7 97.39,51.7
+1V8 on BOTTOM_L10 "NONET_L04_P-001" (solid, remove dead copper, pour order 88): 18.606,83.543 16.555,83.543 16.555,85.414 20.416,85.414 20.095,85.414 20.095,82.322 21.574,82.322 21.574,80.628 18.606,80.628
+3V3 on BOTTOM_L10 "+3V3_L10_P075" (solid, remove dead copper, pour order 75): 20.4,141.3 20.4,131.9 35,131.9 35,134.3 31.2,138.1 25.1,138.1 24.7,138.5 24.7,139.4 25.4,140.1 25.4,141.3
7V-24V on BOTTOM_L10 "7V-24V_L10_P094" (solid, remove dead copper, pour order 94): 19.65,136.858 19.65,146.7 16.99,146.7 16.99,136.858
+3V3 on L5 "NONET_L-01_P-001" (solid, remove dead copper, pour order 99): 0,1 0,159 cw(c1,159) 1,160 91.749,160 94,157.749 94,126 100,120 100,8 96,4 96,1 cw(c95,1) 95,0 1,0 cw(c1,1)
7V-24V on L5 "NONET_L-01_P-001" (solid, remove dead copper, pour order 71): 74.691,47.036 76.88,49.225 76.88,80.08 87.802,91.002 87.802,98.246 98.202,98.246 98.202,127.836 78.602,127.836 78.602,95.472 70.355,87.183 70.355,65.094 65.802,60.541 65.802,47.036
SOM_VREG_MDPX3_1P8 on L5 "NONET_L04_P-001" (solid, remove dead copper, pour order 18): 44.955,49.714 44.955,57.614 51.655,64.314 63.314,64.314 67.555,68.555 67.555,98.887 63.744,98.887 63.744,113.314 54.412,113.314 54.412,98.292 65.255,87.449 65.255,71.314 61.255,67.314 48.483,67.314 42.286,61.116 42.286,49.714
NetC210_2 on L5 "NETC210_2_L05_P054" (solid, remove dead copper, pour order 54): 70.87,38.35 70.87,26.75 78.7,26.75 78.7,38.35
7V-24V on L5 "NONET_L-01_P-001" (solid, remove dead copper, pour order 68): 88.802,116.636 88.802,121.436 94.002,121.436 94.002,160 67.999,160 48.849,160 14.1,160 14.1,136.842 21.083,136.842 29.45,145.209 49.04,145.209 66.975,145.209 70.456,148.69 78.602,148.69 78.602,116.636
+1V8 on L5 "NONET_L04_P-001" (solid, remove dead copper, pour order 85): 37.226,94 37.226,85.294 16.498,85.294 16.498,81.2 52.726,81.2 59.026,74.9 64.326,74.9 64.326,78.5 62.026,80.8 59.626,80.8 52.826,87.6 52.826,94 39.026,94
+3V3 on L5 "NONET_L-01_P-001" (solid, remove dead copper, pour order 61): 21.1,99.065 21.1,117.841 31.9,128.641 31.9,138.465 24.9,138.465 20.7,134.265 18.665,132.23 11.3,132.23 11.3,99.065
NetD4_C on L5 "NETD4_C_L05_P003" (solid, remove dead copper, pour order 3): 83.277,79.874 82.289,80.863 82.289,81.558 91.749,91.019 91.749,101.7 88.521,101.7 88.521,90.721 81.121,83.321 81.121,78.091 83.221,78.091
NetC76_1 on L5 "NONET_L04_P-001" (solid, remove dead copper, pour order 79): 7.394,86.365 0,86.365 0,129.668 7.394,129.668
SOM_VREG_MDPX3_1P8 on L5 "NONET_L04_P-001" (solid, remove dead copper, pour order 23): 13.955,84.114 16.355,84.114 16.355,85.431 36.995,85.431 36.995,90.514 26.755,90.514 26.755,86.914 13.955,86.914
NetC16_2 on L5 "NETC16_2_L05_P051" (solid, remove dead copper, pour order 51): 66.75,4.258 66.75,11.008 73.2,11.008 73.2,4.258
GND on L5 "GND_L05_P010" (solid, remove dead copper, pour order 10): 10.2,0 10.2,38.781 8.392,40.589 8.392,46 0,46 0,49.668 8.628,49.668 12.5,45.795 12.5,0
7V-24V on L5 "NONET_L04_P-001" (solid, remove dead copper, pour order 48): 48.175,4.319 48.175,6.319 50.634,6.319 50.634,4.319
GND on TOP_L1 "NONET_L-01_P-001" (solid, remove dead copper, pour order 82): 0,1 0,159 cw(c1,159) 1,160 91.749,160 94,157.749 94,126 100,120 100,8 96,4 96,1 cw(c95,1) 95,0 1,0 cw(c1,1)
+1V8 on TOP_L1 "NONET_L04_P-001" (solid, remove dead copper, pour order 38): 75.326,64.5 72.826,64.5 72.845,62.2 71.476,62.2 71.126,61.8 71.126,54.3 77.926,54.3 77.926,53.4 78.826,52.5 81.726,52.5 84.226,50 85.326,50 85.626,49.7 85.626,48.2 84.992,47.566 75.761,47.566 75.026,48.3 75.026,49.587 74.295,50.319 71.046,50.319 69.526,51.838 69.526,65.2 70.426,66.1 74.826,66.1 75.326,65.6
+3V3 on TOP_L1 "NONET_L04_P-001" (solid, remove dead copper, pour order 29): 84.384,132.645 93.984,132.645 93.984,159.845 5.984,159.845 5.984,150.659 6.998,149.645 9.184,149.645 9.184,156.245 25.503,156.245 25.503,152.34 28.103,152.34 28.103,156.384 84.384,156.384 84.384,139.245
+3V3_LIMITED on TOP_L1 "NONET_L04_P-001" (solid, remove dead copper, pour order 31): 9.171,55.851 0,55.851 0,76.114 4.575,76.114 4.575,79.666 7.755,79.666 7.755,58.214 9.196,58.214
+5V_LIMITED on TOP_L1 "+5V_LIMITED_L01_P059" (solid, remove dead copper, pour order 59): 12.445,70.36 12.445,59.25 7.602,59.25 7.602,70.36
NetC224_2 on TOP_L1 "NONET_L04_P-001" (solid, remove dead copper, pour order 60): 33.691,23.153 28.517,23.153 28.04,23.63 28.04,45.43 35.44,45.43 35.44,39.991 32.245,36.796 32.258,30.112 33.634,28.736
NetC76_1 on TOP_L1 "NONET_L-01_P-001" (solid, remove dead copper, pour order 62): 6.835,109.925 6.835,115.765 3.9,115.765 3.9,109.925
+1V8 on TOP_L1 "NONET_L04_P-001" (solid, remove dead copper, pour order 33): 62.126,71.174 69.8,63.5 75.526,63.5 75.526,71.574 67.7,79.4 62.126,79.4
NetC76_1 on TOP_L1 "NONET_L-01_P-001" (solid, remove dead copper, pour order 78): 6.543,95.765 6.543,104.265 3.901,104.265 3.901,95.765
+1V8 on TOP_L1 "NONET_L04_P-001" (solid, remove dead copper, pour order 34): 15.126,86.2 15.126,82.373 20.826,82.373 20.826,86.2
+3V3 on TOP_L1 "+3V3_L01_P043" (solid, remove dead copper, pour order 43): 12.01,78.45 12.01,77.95 12.91,77.95 12.91,77.75 12.51,77.75 12.51,75.15 14.728,75.15 14.728,78.45
NetC76_1 on TOP_L1 "NONET_L-01_P-001" (solid, remove dead copper, pour order 73): 6.835,126.1 7.4,126.665 10.5,126.665 11.9,128.065 11.9,130.02 8.155,130.02 7.4,129.265 2.269,129.265 2.269,121.225 6.835,121.225
SOM_VREG_MDPX3_1P8 on L6 "NONET_L-01_P-001" (solid, remove dead copper, pour order 86): 0,1 0,159 cw(c1,159) 1,160 91.749,160 94,157.749 94,126 100,120 100,8 96,4 96,1 cw(c95,1) 95,0 1,0 cw(c1,1)
+3V3_LIMITED on L6 "NONET_L04_P-001" (solid, remove dead copper, pour order 80): 0,80.893 7.55,80.893 7.55,60.814 39.055,60.814 39.055,52.666 15.341,52.666 15.341,48.406 16.906,46.842 19.628,46.842 21.055,45.415 21.055,18.314 26.813,12.556 39.452,12.556 39.452,0 10.41,0 10.41,37.598 0,37.598 0,65.082
+5V on L6 "+5V_L06_P052" (solid, remove dead copper, pour order 52): 100,26 100,71.585 78.362,71.585 78.362,80 84.626,80 84.626,82.597 78.307,88.916 78.362,109.1 22.07,109.1 22.07,96.885 12.262,96.885 12.121,72.435 7.874,72.435 7.874,65.314 61.206,65.314 78.72,47.8 85.026,47.8 85.026,34.7 92.225,34.7 92.225,26
DVDD18 on L6 "DVDD18_L06_P045" (solid, remove dead copper, pour order 45): 73.333,14.698 73.333,4.439 65.565,4.439 65.565,15.299 60.737,15.299 60.737,2.039 76.965,2.039 76.965,14.704
+1V1 on L6 "+1V1_L06_P047" (solid, remove dead copper, pour order 47): 37.37,37.65 37.37,28.919 59.296,28.919 64.381,23.835 64.381,17.912 65.554,16.739 65.554,9.967 65.554,4.59 73.086,4.59 73.086,13.263 75.87,16.047 75.87,27 81.26,27 81.26,41.319 37.37,41.319
PA_VBUS on L6 "NONET_L-01_P-001" (solid, remove dead copper, pour order 76): 99.524,83.257 90.948,83.257 88.328,85.877 88.328,88.329 89.146,89.147 91.853,89.147 94,91.294 94,110.049 92.724,111.325 86.924,111.325 85.924,112.325 85.924,120.125 94,128.201 94,157.712 91.712,160 68.027,160 49.049,160 0,160 0,133.7 30.2,133.7 41.665,145.165 49.034,145.165 66.964,145.165 70.49,148.691 78.601,148.691 78.924,148.368 78.924,75.219 82.219,71.925 99.524,71.925
+5V_LIMITED on L6 "NONET_L04_P-001" (solid, remove dead copper, pour order 24): 7.815,65.014 7.815,61.034 39.36,61.034 39.36,52.514 58.755,52.514 58.755,65.014 8.355,65.014
GND on L6 "GND_L06_P011" (solid, remove dead copper, pour order 11): 10.2,0 10.2,38.781 8.392,40.589 8.392,46 0,46 0,49.668 8.628,49.668 12.5,45.795 12.5,0
GND on L3 "NONET_L-01_P-001" (solid, remove dead copper, pour order 77): 0,1 0,159 cw(c1,159) 1,160 91.749,160 94,157.749 94,126 100,120 100,8 96,4 96,1 cw(c95,1) 95,0 1,0 cw(c1,1)
SOM_VREG_MDPX3_1P8 on L3 "NONET_L04_P-001" (solid, remove dead copper, pour order 21): 12.246,26.114 12.246,4.179 21.055,4.179 21.055,26.114
GND on L2 "NONET_L-01_P-001" (solid, remove dead copper, pour order 20): 0,1 0,159 cw(c1,159) 1,160 91.749,160 94,157.749 94,126 100,120 100,8 96,4 96,1 cw(c95,1) 95,0 1,0 cw(c1,1)
GND on L4 "NONET_L-01_P-001" (solid, remove dead copper, pour order 22): 0,1 0,159 cw(c1,159) 1,160 91.749,160 94,157.749 94,126 100,120 100,8 96,4 96,1 cw(c95,1) 95,0 1,0 cw(c1,1)
GND on L7 "NONET_L-01_P-001" (solid, remove dead copper, pour order 25): 0,1 0,159 cw(c1,159) 1,160 91.749,160 94,157.749 94,126 100,120 100,8 96,4 96,1 cw(c95,1) 95,0 1,0 cw(c1,1)
GND on L9 "NONET_L-01_P-001" (solid, remove dead copper, pour order 27): 0,1 0,159 cw(c1,159) 1,160 91.749,160 94,157.749 94,126 100,120 100,8 96,4 96,1 cw(c95,1) 95,0 1,0 cw(c1,1)

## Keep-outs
TOP_L1:
  circle w0.254: c14.117,6.6 r2.65
  circle w0.254: c3.5,156 r2.65
  circle w0.254: c90,156 r2.65
  circle w0.254: c92,4 r2.65
  circle w0.254: c3.5,59 r2.65
  circle w0.254: c61.5,59 r2.65
BOTTOM_L10:
  circle w0.254: c14.117,6.6 r2.65
  circle w0.254: c3.5,156 r2.65
  circle w0.254: c90,156 r2.65
  circle w0.254: c92,4 r2.65
  circle w0.254: c61.5,59 r2.65
  circle w0.254: c3.5,59 r2.65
